(* Logix 5000 project; controller Electronic_Displays vendor 1 type 14 code 65 rev 17.4; software revision 17.01 *)
// Electronic Displays, Inc.
// Test PLC for Anybus Communicator

TASK MainTask (continuous, watchdog 500 ms) : MainProgram

MODULES
   Controller : vendor 1 type 14 code 65 (CompactLogixL35Controller 0, rev 17.4)
      LocalENB : 1769-L35E Ethernet Port (CompactLogixL35Ethernet 1, rev 17.2)
         AlphaScroller_LEDSIGN : ETHERNET-MODULE (Ethernet 192.168.1.14, rev 1.1, Output RPI 10 ms)   // Anybus Communicator with Alpha Scroller Sign
         AlphaStatic_LEDSIGN : ETHERNET-MODULE (Ethernet 192.168.1.13, rev 1.1, Output RPI 10 ms)   // Anybus Communicator with Alpha Static Sign
         ED202_LEDSIGN : ETHERNET-MODULE (Ethernet 192.168.1.12, rev 1.1, Output RPI 10 ms)   // Anybus Communicator with Numeric Sign
         EDV_LEDSIGN : ETHERNET-MODULE (Ethernet 192.168.1.11, rev 1.1, Output RPI 10 ms)   // Anybus Communicator with EDV-111
      Local : CompactBus (CompactVirtualAdapter 3, rev 17.2, Input RPI 5 ms)
END_MODULES

TYPE ALPHASCROLL :
STRUCT
   Address : STRING;   // "001"=sign address 1 "002"=sign address 2 "003"=sign address 3 etc... per protocol [must be three digits]
   TextMessage : STRING;   // Actual Text Message
   PacketSent : STRING;   // The actual packet sent to the sign.
END_STRUCT
END_TYPE

TYPE ALPHASTATIC :
STRUCT
   Address : STRING;   // "01"=sign address 1 "02"=sign address 2 "03"=sign address 3 etc... per protocol [must be three digits]
   TextMessage : STRING;   // Actual Text Message
   PacketSent : STRING;   // The actual packet sent to the sign.
END_STRUCT
END_TYPE

TYPE LEDSIGN :
STRUCT
   Address : STRING;   // "00"=all signs "01"=sign address 1 "02"=sign address 2 etc... per protocol [must be two digits]
   CommandCode : STRING;   // "A"=write restart "B"=write variable "C"=special "D"=write no restart
   FileLabel : STRING;   // Default is = A
   Text1Message : STRING;   // Actual Text Line 1
   Text2Message : STRING;   // Actual Text Line 2
   Text3Message : STRING;   // Actual Text Line 3
   Text4Message : STRING;   // Actual Text Line 4
   TextFont : STRING;   // "0"=SS7 "1"=SF7 "2"=SF10 "3"=SS16 "4"=SF16
   TextColor : STRING;   // "0"=Red "1"=Green "2"=Yellow "3"=Rainbow
   TextAlign : STRING;   // "M"=middle line "T"=top line "B"=bottom line "F"=fill (best for variables) "L"=left "R"=right
   TextAttribute : STRING;   // "0"=flashing off "1"=flashing on "2"=wide off "3"=wide on "4"=bold off "5"=bold on
   TextEffect : STRING;   // "S"=scrolls "H"=hold "F"=flash "A"=slide up "B"=slide down "C"=slide left "D"=slide right "a"=roll up "b"=roll down "c"=roll left "d"=roll right
   TextSpeed : STRING;   // Options = 1 - 8, 3:Default 1=Fast 8=Slow
   TextPause : STRING;   // Options = 00 - 99, 02:Default defined in seconds [must be two digits] if not will not work!
   Variable1Name : STRING;   // Name of variable Default is = U
   Variable2Name : STRING;   // Name of variable Default is = V
   Variable3Name : STRING;   // Name of variable Default is = W
   Variable4Name : STRING;   // Name of variable Default is = X
   Variable1Value : STRING;   // Actual Variable1 to be Sent (text format)
   Variable2Value : STRING;   // Actual Variable2 to be Sent (text format)
   Variable3Value : STRING;   // Actual Variable3 to be Sent (text format)
   Variable4Value : STRING;   // Actual Variable4 to be Sent (text format)
   VariableFont : STRING;   // "0"=SS7 "1"=SF7 "2"=SF10 "3"=SS16 "4"=SF16
   VariableColor : STRING;   // "0"=Red "1"=Green "2"=Yellow "3"=Rainbow
   VariableAttribute : STRING;   // "0"=flashing off "1"=flashing on "2"=wide off "3"=wide on "4"=bold off "5"=bold on
   Packet1Sent : STRING;   // The actual packet sent to the sign. (Packet1)
   Packet2Sent : STRING;   // The actual packet sent to the sign. (Packet2)
   Packet3Sent : STRING;   // The actual packet sent to the sign. (Packet3)
   Packet4Sent : STRING;   // The actual packet sent to the sign. (Packet4)
   Packet5Sent : STRING;   // The actual packet sent to the sign. (Packet5)
   Packet6Sent : STRING;   // The actual packet sent to the sign. (Packet6)
   ExpertPacket1 : STRING;   // Raw Packet1 to be sent to sign for the expert users. (82 Characters max)
   ExpertPacket2 : STRING;   // Raw Packet2 to be sent to sign for the expert users. (82 Characters max)
   ExpertPacket3 : STRING;   // Raw Packet3 to be sent to sign for the expert users. (82 Characters max)
   ExpertPacket4 : STRING;   // Raw Packet4 to be sent to sign for the expert users. (82 Characters max)
   ExpertPacket5 : STRING;   // Raw Packet5 to be sent to sign for the expert users. (82 Characters max)
   ExpertPacket6 : STRING;   // Raw Packet6 to be sent to sign for the expert users. (82 Characters max)
END_STRUCT
END_TYPE

TYPE NUMSIGN :
STRUCT
   Address : STRING;   // "01"=sign address 1 "02"=sign address 2 etc... per protocol [must be two digits]
   NumberValue : DINT;   // Actual Number to Send to Sign (DINT Format)
   PacketSent : STRING;   // The actual packet sent to the sign.
END_STRUCT
END_TYPE

ADD_ON_INSTRUCTION AlphaScrollerSign   (* revision 1.0, ExecuteEnableInFalse *)
// Alpha Scroller Sign
// Revision note:
// Original Release
// 06-02-2013
// c.elston
VAR_IN_OUT
   Address : STRING; {required}   // "001" = address 01 "002" = address 02 "003" = address 03 etc...(see protocol) must be three digits
   TextMessage : STRING; {required}   // Actual Text Message to be Written to Screen
END_VAR
VAR_OUTPUT
   EN : BOOL; {visible}   // Instruction Interface Enable Bit
   DN : BOOL; {visible}   // Instruction Interface Done Bit
   IP : BOOL; {visible}   // Instruction Interface InProcess Bit
   ER : BOOL; {visible}   // Instruction Interface Error Bit
END_VAR
VAR_IN_OUT
   map_SignInput : SINT[32]; {required}   // Ethernet/IP LEDSIGN.I Data I/O Mapping
   map_SignOutput : SINT[496]; {required}   // Ethernet/IP LEDSIGN.O Data I/O Mapping
   PacketSent : STRING; {required}   // The actual packet sent to the sign (Packet1)
END_VAR
VAR
   SEQ : DINT;   // Sequence Number
   OktoCycle : BOOL;   // Ok to Cycle
   InCycle : BOOL;   // Incycle
   Error : BOOL;   // Error
   Enabled : BOOL;   // Enable ON Bit
   Done : BOOL;   // Done
   Disabled : BOOL;   // Disabled OFF Bit
   SignStartCommand : STRING := '$04';   // DO NOT EDIT = $04
   SignTextMessage : STRING;
   SignAddress : STRING;
   SignEndCommand : STRING := '$12';   // DO NOT EDIT = $12
   Packet : STRING[7];   // Packet Array to send to sign
   SignAddressCommand : STRING := '$07';   // DO NOT EDIT = $07
   SignNULL : STRING;
   Select : DINT;   // Packet Array Select
   TotalPacketCount : DINT[7];   // Total Character Count
   PacketMax : DINT := 82;   // Max Packet Count
   PacketCount : DINT[7];
   Packet6Offset : DINT;
   Packet5Offset : DINT;
   Packet4Offset : DINT;
   Packet3Offset : DINT;
   Packet2Offset : DINT;
   Packet1Offset : DINT;
   SignMessageNumber : STRING := '01';   // DO NOT EDIT = 01
   SignMessageCommand : STRING := '$0A';   // DO NOT EDIT = $0A
END_VAR

ROUTINE EnableInFalse   (* ladder *)
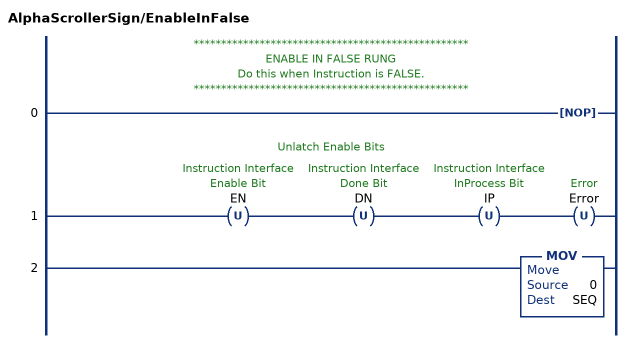
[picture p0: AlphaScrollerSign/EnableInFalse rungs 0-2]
   // **************************************************
   // ENABLE IN FALSE RUNG
   // Do this when Instruction is FALSE.
   // **************************************************
   0: NOP();
   // Unlatch Enable Bits
   1: OTU(EN)OTU(DN)OTU(IP)OTU(Error);
   2: MOV(0,SEQ);
END_ROUTINE

ROUTINE Logic   (* ladder *)
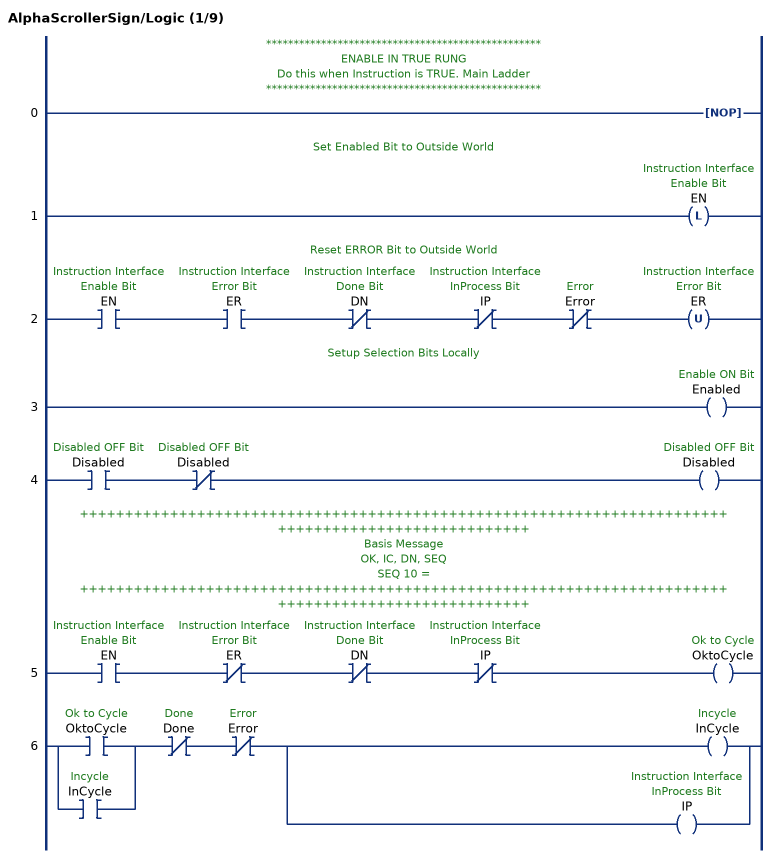
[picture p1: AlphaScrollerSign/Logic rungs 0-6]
   // **************************************************
   // ENABLE IN TRUE RUNG
   // Do this when Instruction is TRUE. Main Ladder
   // **************************************************
   0: NOP();
   // Set Enabled Bit to Outside World
   1: OTL(EN);
   // Reset ERROR Bit to Outside World
   2: XIC(EN)XIC(ER)XIO(DN)XIO(IP)XIO(Error)OTU(ER);
   // Setup Selection Bits Locally
   3: OTE(Enabled);
   4: XIC(Disabled)XIO(Disabled)OTE(Disabled);
   // ++++++++++++++++++++++++++++++++++++++++++++++++++++++++++++++++++++++++++++++++++++++++++++++++++++
   // Basis Message
   // OK, IC, DN, SEQ
   // SEQ 10 =
   // ++++++++++++++++++++++++++++++++++++++++++++++++++++++++++++++++++++++++++++++++++++++++++++++++++++
   5: XIC(EN)XIO(ER)XIO(DN)XIO(IP)OTE(OktoCycle);
   6: [XIC(OktoCycle) ,XIC(InCycle) ]XIO(Done)XIO(Error)[OTE(InCycle) ,OTE(IP) ];
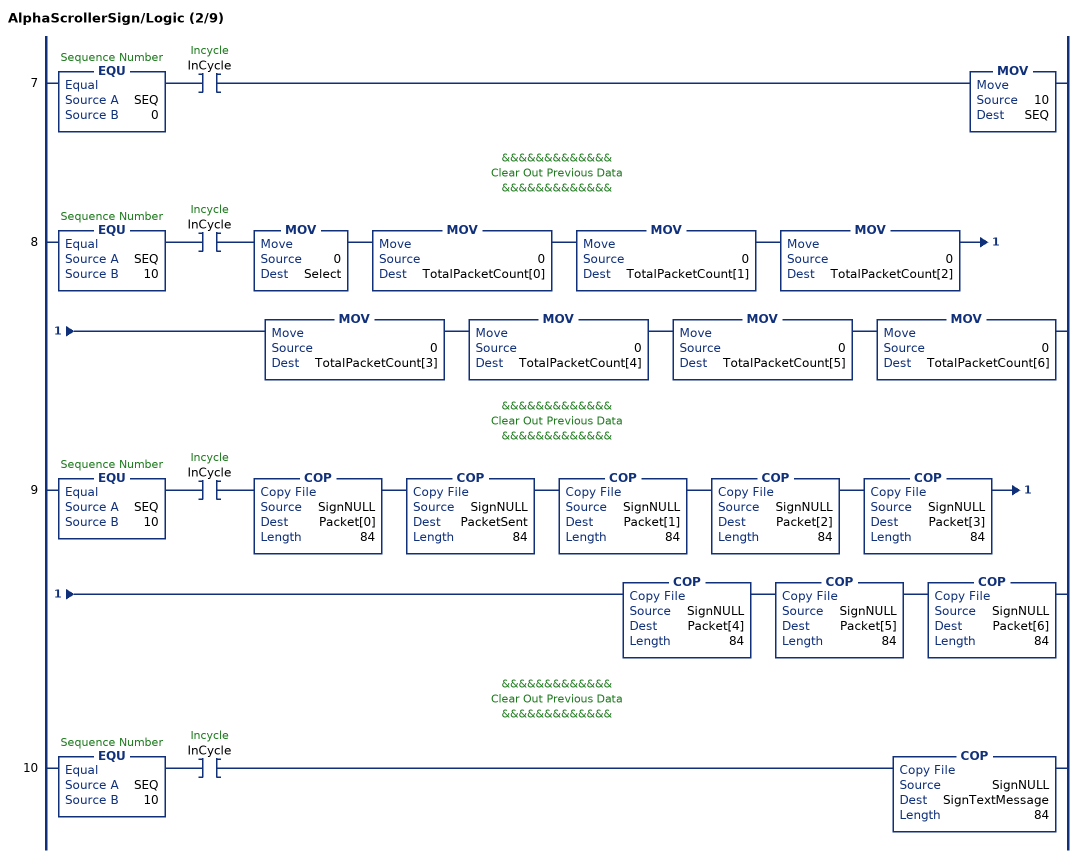
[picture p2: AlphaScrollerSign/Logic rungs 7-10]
   7: EQU(SEQ,0)XIC(InCycle)MOV(10,SEQ);
   // &&&&&&&&&&&&&
   // Clear Out Previous Data
   // &&&&&&&&&&&&&
   8: EQU(SEQ,10)XIC(InCycle)MOV(0,Select)MOV(0,TotalPacketCount[0])MOV(0,TotalPacketCount[1])MOV(0,TotalPacketCount[2])MOV(0,TotalPacketCount[3])MOV(0,TotalPacketCount[4])MOV(0,TotalPacketCount[5])MOV(0,TotalPacketCount[6]);
   // &&&&&&&&&&&&&
   // Clear Out Previous Data
   // &&&&&&&&&&&&&
   9: EQU(SEQ,10)XIC(InCycle)COP(SignNULL,Packet[0],84)COP(SignNULL,PacketSent,84)COP(SignNULL,Packet[1],84)COP(SignNULL,Packet[2],84)COP(SignNULL,Packet[3],84)COP(SignNULL,Packet[4],84)COP(SignNULL,Packet[5],84)COP(SignNULL,Packet[6],84);
   // &&&&&&&&&&&&&
   // Clear Out Previous Data
   // &&&&&&&&&&&&&
   10: EQU(SEQ,10)XIC(InCycle)COP(SignNULL,SignTextMessage,84);
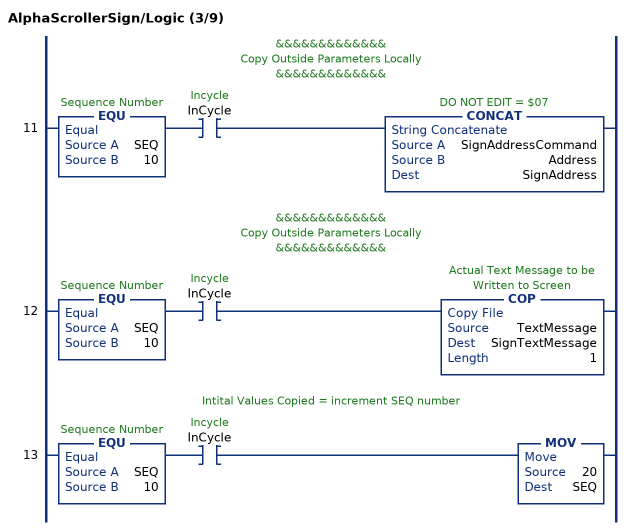
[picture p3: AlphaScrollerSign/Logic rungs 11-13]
   // &&&&&&&&&&&&&
   // Copy Outside Parameters Locally
   // &&&&&&&&&&&&&
   11: EQU(SEQ,10)XIC(InCycle)CONCAT(SignAddressCommand,Address,SignAddress);
   // &&&&&&&&&&&&&
   // Copy Outside Parameters Locally
   // &&&&&&&&&&&&&
   12: EQU(SEQ,10)XIC(InCycle)COP(TextMessage,SignTextMessage,1);
   // Intital Values Copied = increment SEQ number
   13: EQU(SEQ,10)XIC(InCycle)MOV(20,SEQ);
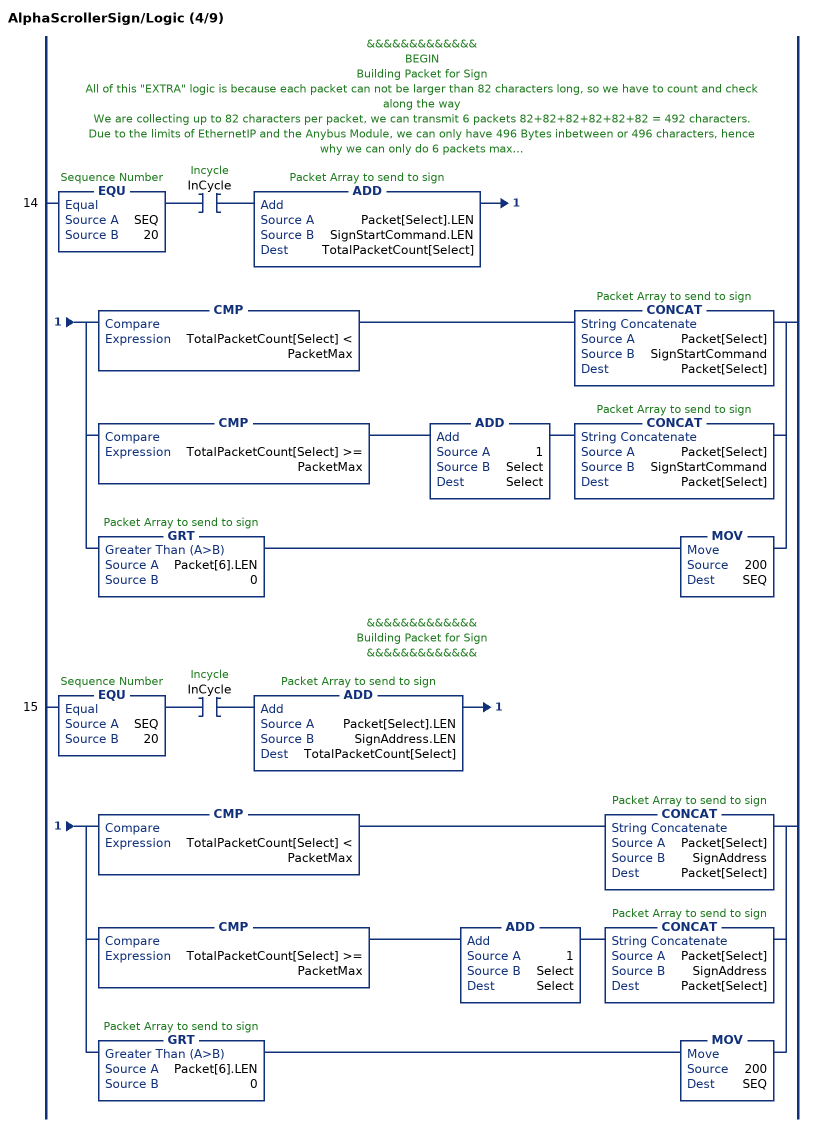
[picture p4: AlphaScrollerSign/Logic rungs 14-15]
   // &&&&&&&&&&&&&
   // BEGIN
   // Building Packet for Sign
   // All of this "EXTRA" logic is because each packet can not be larger than 82 characters long, so we have to count and check along the way
   // We are collecting up to 82 characters per packet, we can transmit 6 packets 82+82+82+82+82+82 = 492 characters.
   // Due to the limits of EthernetIP and the Anybus Module, we can only have 496 Bytes inbetween or 496 characters, hence why we can only do 6 packets max.
   // Once we exceed this, we will fault and ERROR trap any windy typing people.
   // &&&&&&&&&&&&&
   14: EQU(SEQ,20)XIC(InCycle)ADD(Packet[Select].LEN,SignStartCommand.LEN,TotalPacketCount[Select])[CMP(TotalPacketCount[Select] < PacketMax) CONCAT(Packet[Select],SignStartCommand,Packet[Select]) ,CMP(TotalPacketCount[Select] >= PacketMax) ADD(1,Select,Select) CONCAT(Packet[Select],SignStartCommand,Packet[Select]) ,GRT(Packet[6].LEN,0) MOV(200,SEQ) ];
   // &&&&&&&&&&&&&
   // Building Packet for Sign
   // &&&&&&&&&&&&&
   15: EQU(SEQ,20)XIC(InCycle)ADD(Packet[Select].LEN,SignAddress.LEN,TotalPacketCount[Select])[CMP(TotalPacketCount[Select] < PacketMax) CONCAT(Packet[Select],SignAddress,Packet[Select]) ,CMP(TotalPacketCount[Select] >= PacketMax) ADD(1,Select,Select) CONCAT(Packet[Select],SignAddress,Packet[Select]) ,GRT(Packet[6].LEN,0) MOV(200,SEQ) ];
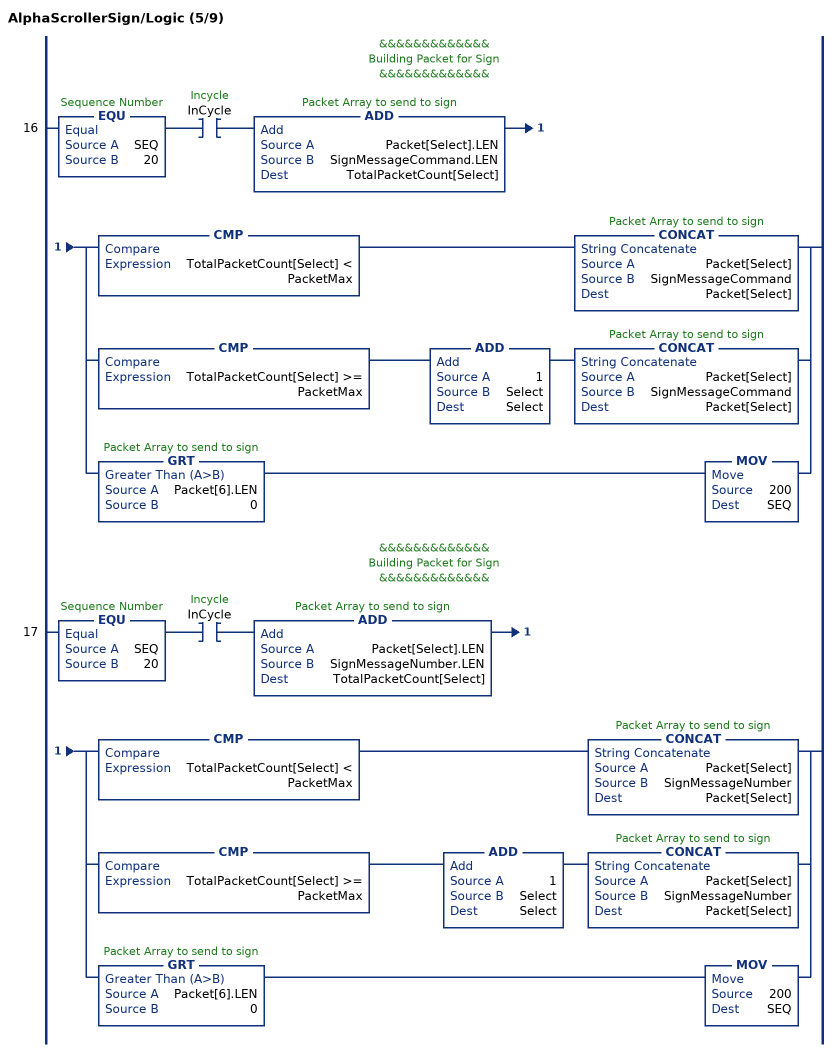
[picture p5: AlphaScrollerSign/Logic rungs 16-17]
   // &&&&&&&&&&&&&
   // Building Packet for Sign
   // &&&&&&&&&&&&&
   16: EQU(SEQ,20)XIC(InCycle)ADD(Packet[Select].LEN,SignMessageCommand.LEN,TotalPacketCount[Select])[CMP(TotalPacketCount[Select] < PacketMax) CONCAT(Packet[Select],SignMessageCommand,Packet[Select]) ,CMP(TotalPacketCount[Select] >= PacketMax) ADD(1,Select,Select) CONCAT(Packet[Select],SignMessageCommand,Packet[Select]) ,GRT(Packet[6].LEN,0) MOV(200,SEQ) ];
   // &&&&&&&&&&&&&
   // Building Packet for Sign
   // &&&&&&&&&&&&&
   17: EQU(SEQ,20)XIC(InCycle)ADD(Packet[Select].LEN,SignMessageNumber.LEN,TotalPacketCount[Select])[CMP(TotalPacketCount[Select] < PacketMax) CONCAT(Packet[Select],SignMessageNumber,Packet[Select]) ,CMP(TotalPacketCount[Select] >= PacketMax) ADD(1,Select,Select) CONCAT(Packet[Select],SignMessageNumber,Packet[Select]) ,GRT(Packet[6].LEN,0) MOV(200,SEQ) ];
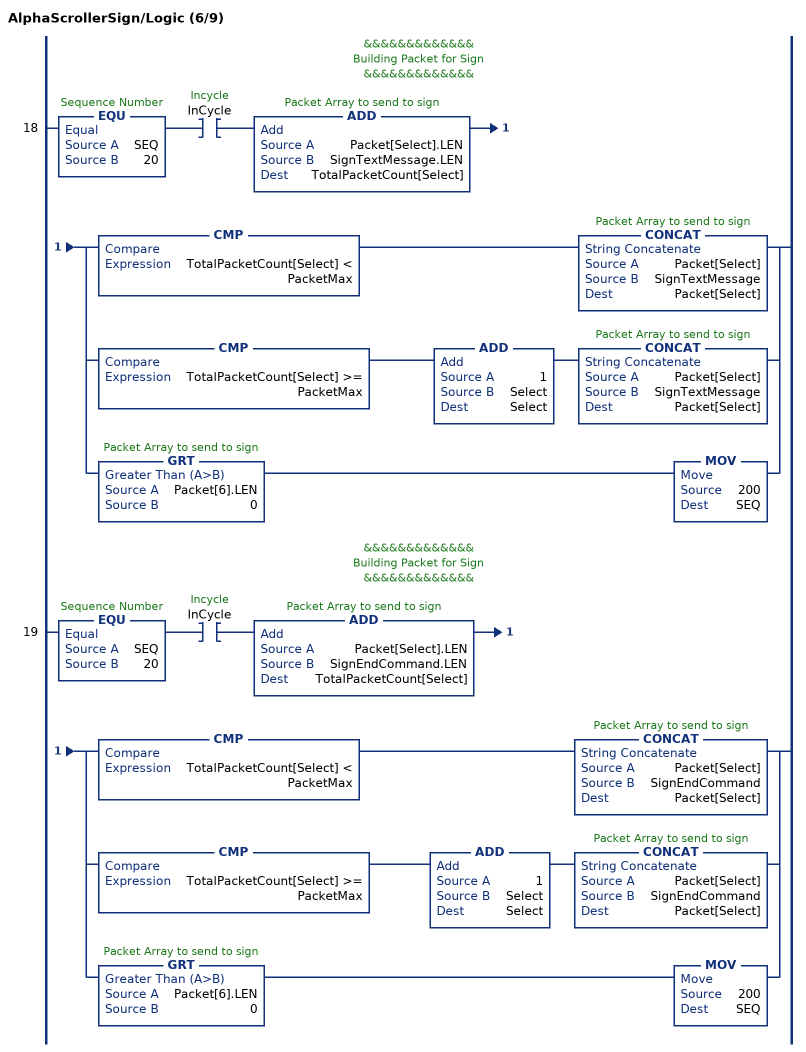
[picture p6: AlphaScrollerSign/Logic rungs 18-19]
   // &&&&&&&&&&&&&
   // Building Packet for Sign
   // &&&&&&&&&&&&&
   18: EQU(SEQ,20)XIC(InCycle)ADD(Packet[Select].LEN,SignTextMessage.LEN,TotalPacketCount[Select])[CMP(TotalPacketCount[Select] < PacketMax) CONCAT(Packet[Select],SignTextMessage,Packet[Select]) ,CMP(TotalPacketCount[Select] >= PacketMax) ADD(1,Select,Select) CONCAT(Packet[Select],SignTextMessage,Packet[Select]) ,GRT(Packet[6].LEN,0) MOV(200,SEQ) ];
   // &&&&&&&&&&&&&
   // Building Packet for Sign
   // &&&&&&&&&&&&&
   19: EQU(SEQ,20)XIC(InCycle)ADD(Packet[Select].LEN,SignEndCommand.LEN,TotalPacketCount[Select])[CMP(TotalPacketCount[Select] < PacketMax) CONCAT(Packet[Select],SignEndCommand,Packet[Select]) ,CMP(TotalPacketCount[Select] >= PacketMax) ADD(1,Select,Select) CONCAT(Packet[Select],SignEndCommand,Packet[Select]) ,GRT(Packet[6].LEN,0) MOV(200,SEQ) ];
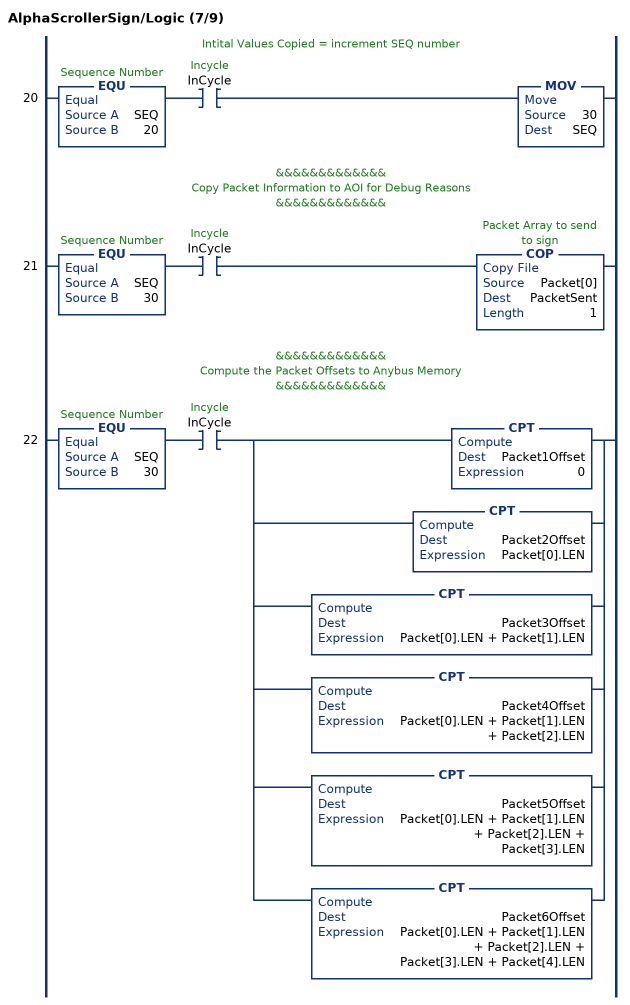
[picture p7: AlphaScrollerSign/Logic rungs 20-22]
   // Intital Values Copied = increment SEQ number
   20: EQU(SEQ,20)XIC(InCycle)MOV(30,SEQ);
   // &&&&&&&&&&&&&
   // Copy Packet Information to AOI for Debug Reasons
   // &&&&&&&&&&&&&
   21: EQU(SEQ,30)XIC(InCycle)COP(Packet[0],PacketSent,1);
   // &&&&&&&&&&&&&
   // Compute the Packet Offsets to Anybus Memory
   // &&&&&&&&&&&&&
   22: EQU(SEQ,30)XIC(InCycle)[CPT(Packet1Offset,0) ,CPT(Packet2Offset,Packet[0].LEN) ,CPT(Packet3Offset,Packet[0].LEN + Packet[1].LEN) ,CPT(Packet4Offset,Packet[0].LEN + Packet[1].LEN + Packet[2].LEN) ,CPT(Packet5Offset,Packet[0].LEN + Packet[1].LEN + Packet[2].LEN + Packet[3].LEN) ,CPT(Packet6Offset,Packet[0].LEN + Packet[1].LEN + Packet[2].LEN + Packet[3].LEN + Packet[4].LEN) ];
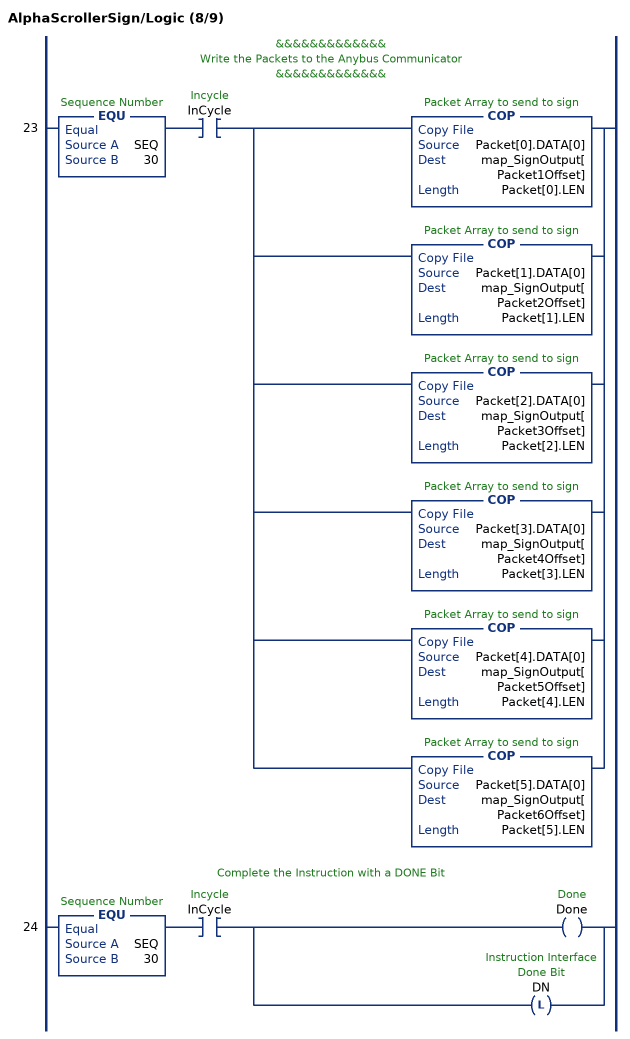
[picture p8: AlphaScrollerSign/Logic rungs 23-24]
   // &&&&&&&&&&&&&
   // Write the Packets to the Anybus Communicator
   // &&&&&&&&&&&&&
   23: EQU(SEQ,30)XIC(InCycle)[COP(Packet[0].DATA[0],map_SignOutput[Packet1Offset],Packet[0].LEN) ,COP(Packet[1].DATA[0],map_SignOutput[Packet2Offset],Packet[1].LEN) ,COP(Packet[2].DATA[0],map_SignOutput[Packet3Offset],Packet[2].LEN) ,COP(Packet[3].DATA[0],map_SignOutput[Packet4Offset],Packet[3].LEN) ,COP(Packet[4].DATA[0],map_SignOutput[Packet5Offset],Packet[4].LEN) ,COP(Packet[5].DATA[0],map_SignOutput[Packet6Offset],Packet[5].LEN) ];
   // Complete the Instruction with a DONE Bit
   24: EQU(SEQ,30)XIC(InCycle)[OTE(Done) ,OTL(DN) ];
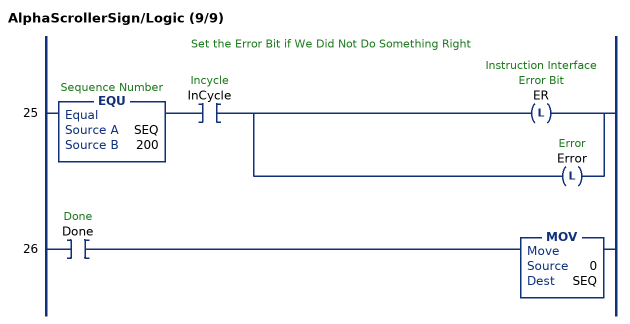
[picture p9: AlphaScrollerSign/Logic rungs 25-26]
   // Set the Error Bit if We Did Not Do Something Right
   25: EQU(SEQ,200)XIC(InCycle)[OTL(ER) ,OTL(Error) ];
   26: XIC(Done)MOV(0,SEQ);
END_ROUTINE
END_ADD_ON_INSTRUCTION

ADD_ON_INSTRUCTION AlphaStaticSign   (* revision 1.0, ExecuteEnableInFalse *)
// Alpha Static Sign
// Revision note:
// Original Release
// 06-02-2013
// c.elston
VAR_IN_OUT
   Address : STRING; {required}   // "01" = address 01 "02" = address 02 etc...(see protocol)
   TextMessage : STRING; {required}   // Actual Text Message to be Written to Screen
END_VAR
VAR_OUTPUT
   EN : BOOL; {visible}   // Instruction Interface Enable Bit
   DN : BOOL; {visible}   // Instruction Interface Done Bit
   ER : BOOL; {visible}   // Instruction Interface Error Bit
   IP : BOOL; {visible}   // Instruction Interface InProcess Bit
END_VAR
VAR_IN_OUT
   map_SignInput : SINT[32]; {required}   // Ethernet/IP LEDSIGN.I Data I/O Mapping
   map_SignOutput : SINT[496]; {required}   // Ethernet/IP LEDSIGN.O Data I/O Mapping
   PacketSent : STRING; {required}   // The actual packet sent to the sign.
END_VAR
VAR
   SEQ : DINT;   // Sequence Number
   OktoCycle : BOOL;   // Ok to Cycle
   InCycle : BOOL;   // Incycle
   Error : BOOL;   // Error
   Enabled : BOOL;   // Enable ON Bit
   Done : BOOL;   // Done
   Disabled : BOOL;   // Disabled OFF Bit
   SignETX : STRING := '$03';   // DO NOT EDIT = $03 the number sign protocol is different than EDV signs
   SignAddress : STRING;
   SignSTX : STRING := '$02';   // DO NOT EDIT = $02 the number sign protocol is different than EDV signs
   SignNULL : STRING;
   TotalPacketCount : DINT[7];   // Total Character Count
   Select : DINT;   // Packet Array Select
   PacketMax : DINT := 82;   // Max Packet Count
   PacketCount : DINT[7];
   Packet6Offset : DINT;
   Packet5Offset : DINT;
   Packet4Offset : DINT;
   Packet3Offset : DINT;
   Packet2Offset : DINT;
   Packet1Offset : DINT;
   Packet : STRING[7];   // Packet Array to send to sign
   SignTextMessage : STRING;
END_VAR

ROUTINE EnableInFalse   (* ladder *)
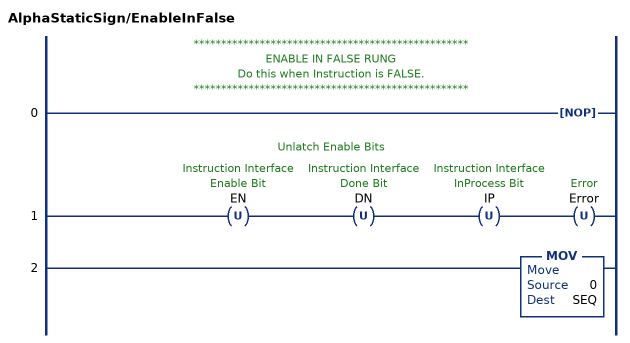
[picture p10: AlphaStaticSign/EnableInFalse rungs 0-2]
   // **************************************************
   // ENABLE IN FALSE RUNG
   // Do this when Instruction is FALSE.
   // **************************************************
   0: NOP();
   // Unlatch Enable Bits
   1: OTU(EN)OTU(DN)OTU(IP)OTU(Error);
   2: MOV(0,SEQ);
END_ROUTINE

ROUTINE Logic   (* ladder *)
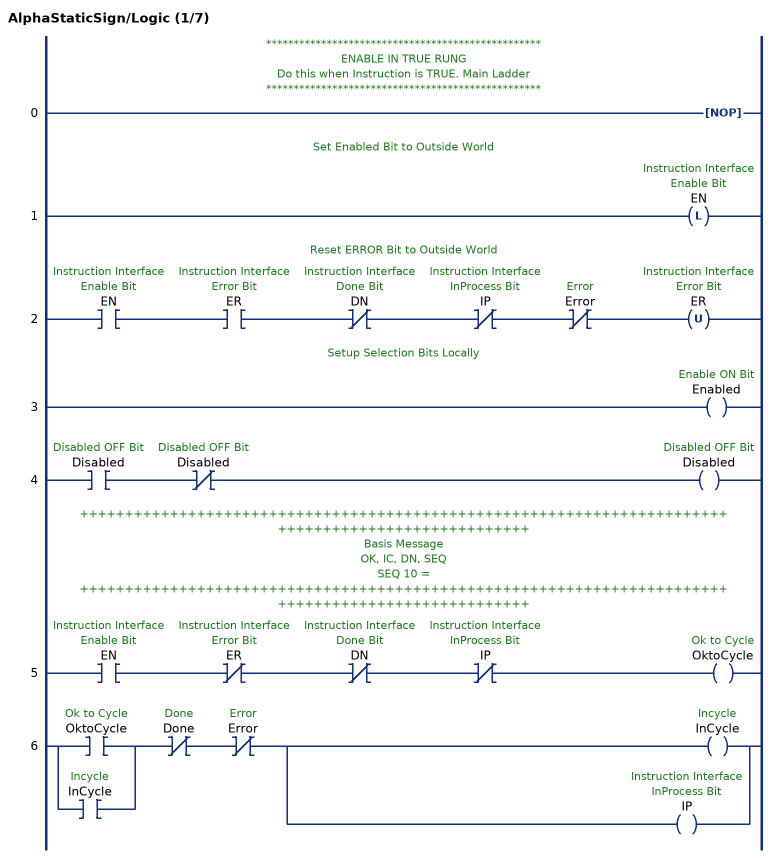
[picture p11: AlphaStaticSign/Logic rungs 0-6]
   // **************************************************
   // ENABLE IN TRUE RUNG
   // Do this when Instruction is TRUE. Main Ladder
   // **************************************************
   0: NOP();
   // Set Enabled Bit to Outside World
   1: OTL(EN);
   // Reset ERROR Bit to Outside World
   2: XIC(EN)XIC(ER)XIO(DN)XIO(IP)XIO(Error)OTU(ER);
   // Setup Selection Bits Locally
   3: OTE(Enabled);
   4: XIC(Disabled)XIO(Disabled)OTE(Disabled);
   // ++++++++++++++++++++++++++++++++++++++++++++++++++++++++++++++++++++++++++++++++++++++++++++++++++++
   // Basis Message
   // OK, IC, DN, SEQ
   // SEQ 10 =
   // ++++++++++++++++++++++++++++++++++++++++++++++++++++++++++++++++++++++++++++++++++++++++++++++++++++
   5: XIC(EN)XIO(ER)XIO(DN)XIO(IP)OTE(OktoCycle);
   6: [XIC(OktoCycle) ,XIC(InCycle) ]XIO(Done)XIO(Error)[OTE(InCycle) ,OTE(IP) ];
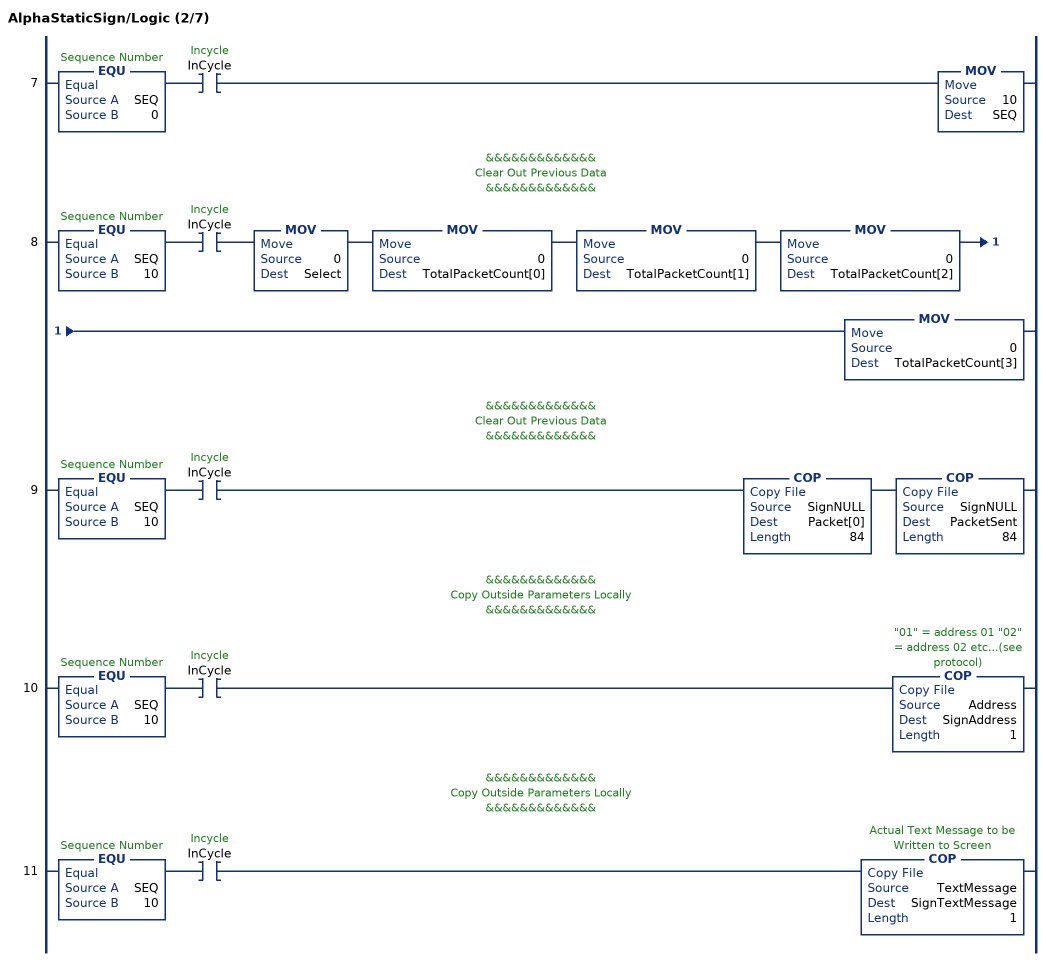
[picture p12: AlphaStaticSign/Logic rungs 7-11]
   7: EQU(SEQ,0)XIC(InCycle)MOV(10,SEQ);
   // &&&&&&&&&&&&&
   // Clear Out Previous Data
   // &&&&&&&&&&&&&
   8: EQU(SEQ,10)XIC(InCycle)MOV(0,Select)MOV(0,TotalPacketCount[0])MOV(0,TotalPacketCount[1])MOV(0,TotalPacketCount[2])MOV(0,TotalPacketCount[3]);
   // &&&&&&&&&&&&&
   // Clear Out Previous Data
   // &&&&&&&&&&&&&
   9: EQU(SEQ,10)XIC(InCycle)COP(SignNULL,Packet[0],84)COP(SignNULL,PacketSent,84);
   // &&&&&&&&&&&&&
   // Copy Outside Parameters Locally
   // &&&&&&&&&&&&&
   10: EQU(SEQ,10)XIC(InCycle)COP(Address,SignAddress,1);
   // &&&&&&&&&&&&&
   // Copy Outside Parameters Locally
   // &&&&&&&&&&&&&
   11: EQU(SEQ,10)XIC(InCycle)COP(TextMessage,SignTextMessage,1);
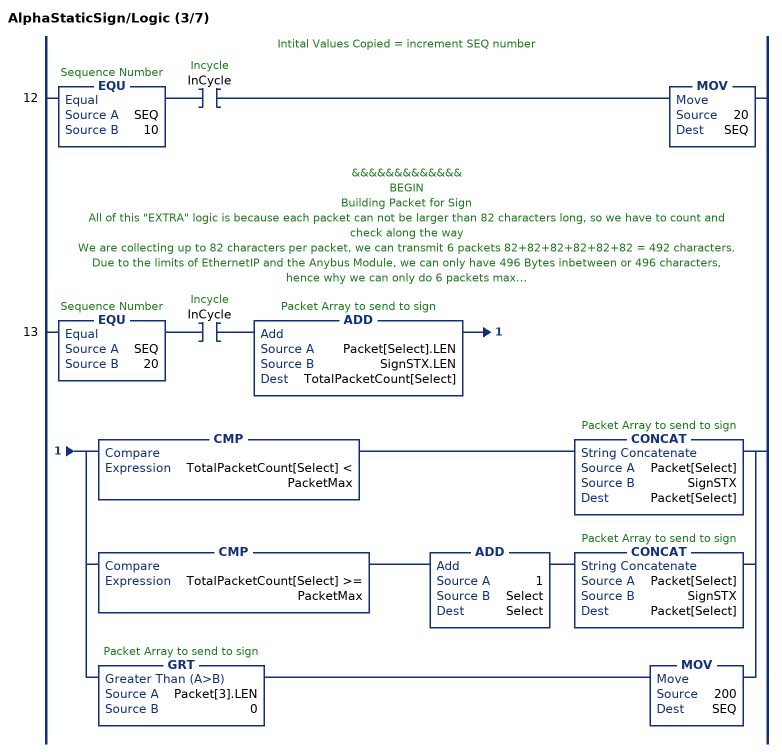
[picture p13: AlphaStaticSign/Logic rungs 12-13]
   // Intital Values Copied = increment SEQ number
   12: EQU(SEQ,10)XIC(InCycle)MOV(20,SEQ);
   // &&&&&&&&&&&&&
   // BEGIN
   // Building Packet for Sign
   // All of this "EXTRA" logic is because each packet can not be larger than 82 characters long, so we have to count and check along the way
   // We are collecting up to 82 characters per packet, we can transmit 6 packets 82+82+82+82+82+82 = 492 characters.
   // Due to the limits of EthernetIP and the Anybus Module, we can only have 496 Bytes inbetween or 496 characters, hence why we can only do 6 packets max.
   // Once we exceed this, we will fault and ERROR trap any windy typing people.
   // In this instruction below, it's so small, we are only using 3 packets max.
   // &&&&&&&&&&&&&
   13: EQU(SEQ,20)XIC(InCycle)ADD(Packet[Select].LEN,SignSTX.LEN,TotalPacketCount[Select])[CMP(TotalPacketCount[Select] < PacketMax) CONCAT(Packet[Select],SignSTX,Packet[Select]) ,CMP(TotalPacketCount[Select] >= PacketMax) ADD(1,Select,Select) CONCAT(Packet[Select],SignSTX,Packet[Select]) ,GRT(Packet[3].LEN,0) MOV(200,SEQ) ];
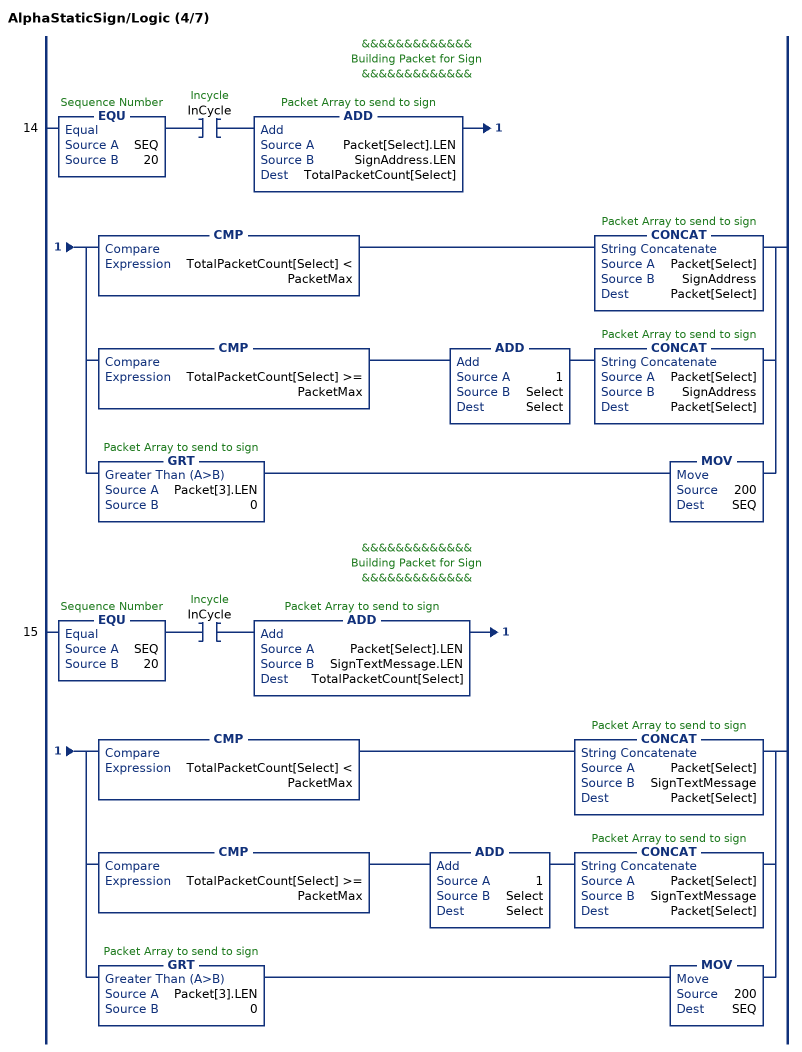
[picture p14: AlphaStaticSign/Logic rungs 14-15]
   // &&&&&&&&&&&&&
   // Building Packet for Sign
   // &&&&&&&&&&&&&
   14: EQU(SEQ,20)XIC(InCycle)ADD(Packet[Select].LEN,SignAddress.LEN,TotalPacketCount[Select])[CMP(TotalPacketCount[Select] < PacketMax) CONCAT(Packet[Select],SignAddress,Packet[Select]) ,CMP(TotalPacketCount[Select] >= PacketMax) ADD(1,Select,Select) CONCAT(Packet[Select],SignAddress,Packet[Select]) ,GRT(Packet[3].LEN,0) MOV(200,SEQ) ];
   // &&&&&&&&&&&&&
   // Building Packet for Sign
   // &&&&&&&&&&&&&
   15: EQU(SEQ,20)XIC(InCycle)ADD(Packet[Select].LEN,SignTextMessage.LEN,TotalPacketCount[Select])[CMP(TotalPacketCount[Select] < PacketMax) CONCAT(Packet[Select],SignTextMessage,Packet[Select]) ,CMP(TotalPacketCount[Select] >= PacketMax) ADD(1,Select,Select) CONCAT(Packet[Select],SignTextMessage,Packet[Select]) ,GRT(Packet[3].LEN,0) MOV(200,SEQ) ];
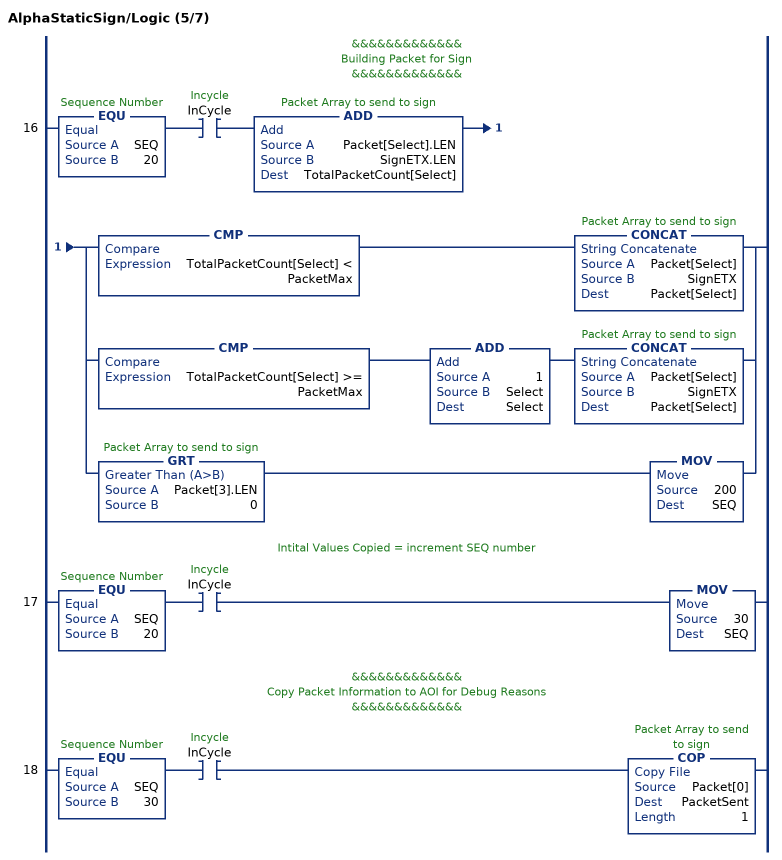
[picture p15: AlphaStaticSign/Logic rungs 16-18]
   // &&&&&&&&&&&&&
   // Building Packet for Sign
   // &&&&&&&&&&&&&
   16: EQU(SEQ,20)XIC(InCycle)ADD(Packet[Select].LEN,SignETX.LEN,TotalPacketCount[Select])[CMP(TotalPacketCount[Select] < PacketMax) CONCAT(Packet[Select],SignETX,Packet[Select]) ,CMP(TotalPacketCount[Select] >= PacketMax) ADD(1,Select,Select) CONCAT(Packet[Select],SignETX,Packet[Select]) ,GRT(Packet[3].LEN,0) MOV(200,SEQ) ];
   // Intital Values Copied = increment SEQ number
   17: EQU(SEQ,20)XIC(InCycle)MOV(30,SEQ);
   // &&&&&&&&&&&&&
   // Copy Packet Information to AOI for Debug Reasons
   // &&&&&&&&&&&&&
   18: EQU(SEQ,30)XIC(InCycle)COP(Packet[0],PacketSent,1);
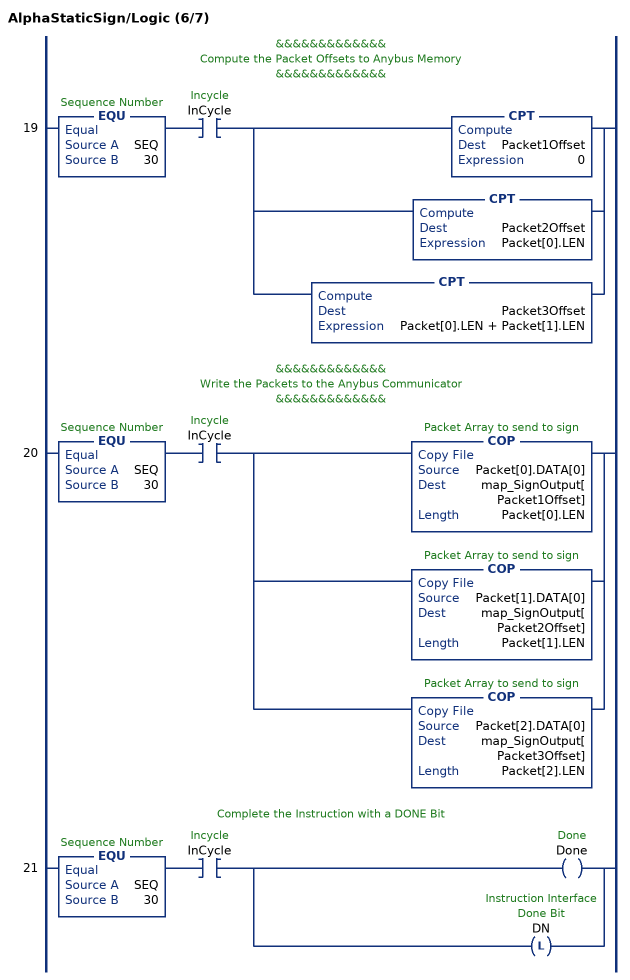
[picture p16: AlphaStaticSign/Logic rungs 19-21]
   // &&&&&&&&&&&&&
   // Compute the Packet Offsets to Anybus Memory
   // &&&&&&&&&&&&&
   19: EQU(SEQ,30)XIC(InCycle)[CPT(Packet1Offset,0) ,CPT(Packet2Offset,Packet[0].LEN) ,CPT(Packet3Offset,Packet[0].LEN + Packet[1].LEN) ];
   // &&&&&&&&&&&&&
   // Write the Packets to the Anybus Communicator
   // &&&&&&&&&&&&&
   20: EQU(SEQ,30)XIC(InCycle)[COP(Packet[0].DATA[0],map_SignOutput[Packet1Offset],Packet[0].LEN) ,COP(Packet[1].DATA[0],map_SignOutput[Packet2Offset],Packet[1].LEN) ,COP(Packet[2].DATA[0],map_SignOutput[Packet3Offset],Packet[2].LEN) ];
   // Complete the Instruction with a DONE Bit
   21: EQU(SEQ,30)XIC(InCycle)[OTE(Done) ,OTL(DN) ];
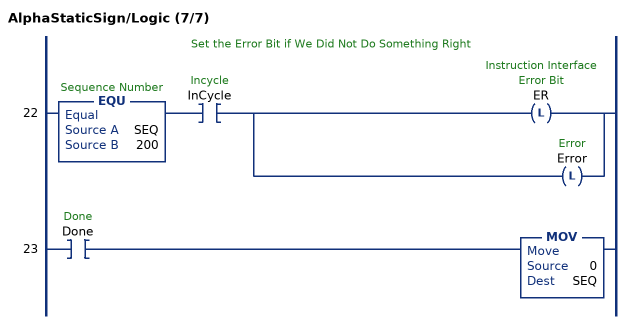
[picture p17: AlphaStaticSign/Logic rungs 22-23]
   // Set the Error Bit if We Did Not Do Something Right
   22: EQU(SEQ,200)XIC(InCycle)[OTL(ER) ,OTL(Error) ];
   23: XIC(Done)MOV(0,SEQ);
END_ROUTINE
END_ADD_ON_INSTRUCTION
